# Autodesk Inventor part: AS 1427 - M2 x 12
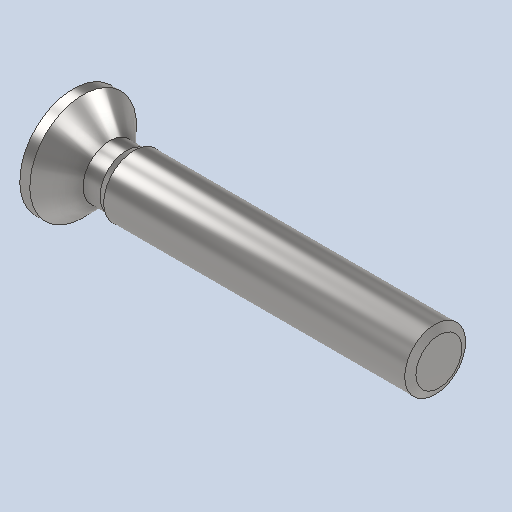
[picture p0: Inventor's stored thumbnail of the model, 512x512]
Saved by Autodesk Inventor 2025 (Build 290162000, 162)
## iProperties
Created: 2024-01
Part Number: AS 1427 - M2 x 12
Material: Acciaio, Dolce
Description: Pozidriv Viti metriche ISO
Document SubType Name: Modeling
Designer: Ryzen5700u
Density: 7.85 g/cm^3
Appearance: Default
Author: Ryzen5700u
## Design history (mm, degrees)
feature "Solid1"
node "Solido1"
